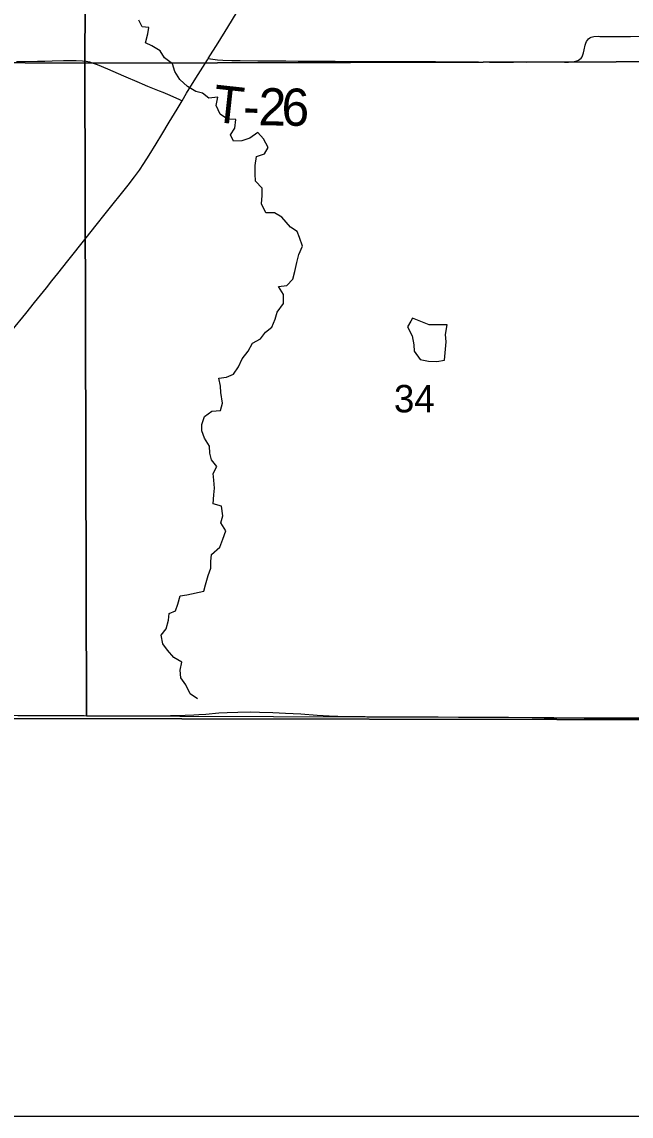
# Model space of a CAD drawing. Extents: x 0 to 34, y 0 to 22.
# Drawn here: x 3.887 to 4.352, y 14.1 to 14.935 of the extents above; entities that cross this region are included whole.
import ezdxf

# ---------------------------------------------------------------- set-up
doc = ezdxf.new("R2010")
doc.units = 0
for name, color, linetype in [('GM_X_Adjacent_County', 7, 'Continuous'), ('GM_X_County', 7, 'Continuous'), ('GM_X_County_Road', 7, 'Continuous'), ('GM_X_Minor_Lake', 7, 'Continuous'), ('GM_X_Minor_River', 7, 'Continuous'), ('GM_X_Section', 7, 'Continuous'), ('GM_X_Section_Text', 7, 'Continuous'), ('GM_X_State_Route', 7, 'Continuous'), ('GM_X_Township', 7, 'Continuous'), ('GM_X_Township_Road', 7, 'Continuous'), ('GM_X_Township_Road_Text', 7, 'Continuous'), ('SH_Data', 7, 'Continuous')]:
    doc.layers.add(name, color=color, linetype=linetype)

msp = doc.modelspace()

# ---------------------------------------------------------------- linework, layer by layer
at = {"layer": 'GM_X_Adjacent_County'}
for points in [[(2.6, 14.40919), (2.6, 14.1), (7.45277, 14.1)], [(7.45277, 14.1), (7.45284, 14.15055), (7.45459, 14.40015), (7.13726, 14.39886), (6.95145, 14.39952), (6.83768, 14.39906), (6.14063, 14.40011), (5.94628, 14.40039), (5.52367, 14.40104), (5.44111, 14.40116), (5.06657, 14.40173), (5.04041, 14.40177), (4.43815, 14.40265), (3.86539, 14.40349), (3.71208, 14.40564), (3.66948, 14.40585), (3.64498, 14.40529), (3.62218, 14.40551), (3.56097, 14.40598), (3.47236, 14.40671), (3.43312, 14.40703), (2.6, 14.40919)]]:
    msp.add_lwpolyline(points, dxfattribs=at)
at = {"layer": 'GM_X_County'}
msp.add_lwpolyline([(2.6, 14.40919), (3.43312, 14.40703), (3.47236, 14.40671), (3.56097, 14.40598), (3.62218, 14.40551), (3.64498, 14.40529), (3.66948, 14.40585), (3.71208, 14.40564), (3.86539, 14.40349), (4.43815, 14.40265)], dxfattribs=at)
at = {"layer": 'GM_X_County_Road'}
msp.add_lwpolyline([(3.88342, 14.40584), (3.8887, 14.40585), (3.8946, 14.40587), (3.89988, 14.40588), (3.90765, 14.40591), (3.91262, 14.40592), (3.91853, 14.40593), (3.92257, 14.40591), (3.92722, 14.40586), (3.93404, 14.40579), (3.93838, 14.40574), (3.94364, 14.40568), (3.95604, 14.40562), (3.9638, 14.40563), (3.97061, 14.40567), (3.97651, 14.40569), (3.98363, 14.4057), (3.98983, 14.4057), (3.99599, 14.40568), (4, 14.40578), (4.00587, 14.40599), (4.01115, 14.4062), (4.01798, 14.40638), (4.0217, 14.40657), (4.02695, 14.40699), (4.03686, 14.40787), (4.04338, 14.40826), (4.05146, 14.40852), (4.0611, 14.40861), (4.06794, 14.40852), (4.0782, 14.40822), (4.08783, 14.40778), (4.09962, 14.40703), (4.11202, 14.40612), (4.12133, 14.40556), (4.12442, 14.40539), (4.12782, 14.40526), (4.13153, 14.40514), (4.14072, 14.40508), (4.1432, 14.40503), (4.14879, 14.40499), (4.15718, 14.40497), (4.16122, 14.40496), (4.16992, 14.40493), (4.17738, 14.40492), (4.18546, 14.40488), (4.19446, 14.40483), (4.20441, 14.40475), (4.21994, 14.40461), (4.22895, 14.40464), (4.23299, 14.40465), (4.24044, 14.40467), (4.24541, 14.40464), (4.25815, 14.40453), (4.27615, 14.40432), (4.28546, 14.4042), (4.29415, 14.40412), (4.30501, 14.40407), (4.30874, 14.40401), (4.31589, 14.40389), (4.32707, 14.40383), (4.33453, 14.40377), (4.34261, 14.40368), (4.35068, 14.40363), (4.36403, 14.40365)], dxfattribs=at)
at = {"layer": 'GM_X_Minor_Lake'}
for points in [[(4.1835, 14.70693), (4.18096, 14.70257), (4.18471, 14.69571), (4.18598, 14.68887), (4.18614, 14.68394), (4.19065, 14.67765), (4.19709, 14.67646), (4.20335, 14.67622), (4.20943, 14.67731)], [(4.20943, 14.67731), (4.21048, 14.69116), (4.21014, 14.69685), (4.21133, 14.70405), (4.20469, 14.70429), (4.19767, 14.70415), (4.1848, 14.70918), (4.1835, 14.70693)]]:
    msp.add_lwpolyline(points, dxfattribs=at)
at = {"layer": 'GM_X_Minor_River'}
for points in [[(4.0385, 14.6526), (4.03834, 14.65735), (4.03706, 14.66343), (4.04276, 14.66433), (4.04827, 14.66657), (4.05211, 14.67204), (4.05481, 14.67828), (4.0594, 14.68394), (4.06267, 14.69018), (4.06877, 14.69355), (4.0726, 14.69864), (4.07756, 14.7024), (4.07988, 14.70845), (4.08144, 14.71394), (4.08623, 14.72036), (4.08647, 14.72737), (4.08253, 14.73348), (4.08879, 14.73419), (4.09357, 14.73908), (4.09494, 14.74496), (4.09651, 14.75177), (4.09807, 14.75783), (4.10096, 14.76426), (4.09855, 14.77073), (4.09668, 14.77549), (4.09158, 14.77875), (4.08519, 14.78639), (4.07952, 14.78966), (4.07288, 14.78971), (4.06951, 14.79656), (4.06994, 14.80301), (4.06998, 14.80851), (4.0649, 14.81386), (4.06475, 14.81956), (4.0646, 14.82582), (4.06579, 14.83264), (4.07188, 14.83468), (4.07457, 14.8396), (4.07101, 14.84607), (4.06668, 14.85104), (4.06058, 14.84672), (4.05449, 14.84468), (4.04823, 14.84435), (4.04599, 14.8493), (4.04906, 14.85421), (4.04987, 14.86084), (4.04361, 14.86108), (4.03795, 14.86491), (4.03496, 14.87158), (4.03614, 14.87802), (4.02931, 14.87731), (4.0244, 14.88114), (4.01929, 14.88232), (4.01305, 14.88616), (4.00721, 14.89152), (4.00346, 14.89762), (4.00161, 14.90351), (3.99557, 14.90792), (3.99219, 14.91326), (3.98577, 14.9171), (3.98085, 14.9196), (3.9828, 14.92623), (3.98359, 14.93116), (3.97829, 14.93177), (3.97586, 14.93691)], [(4.02071, 14.41861), (4.01518, 14.42253), (4.01183, 14.4292), (4.00789, 14.43474), (4.00756, 14.44043), (4.00875, 14.44669), (4.00252, 14.45015), (3.99783, 14.4557), (3.99427, 14.46066), (3.99281, 14.46713), (3.99683, 14.47203), (3.99841, 14.47866), (3.99902, 14.48378), (4.00378, 14.48583), (4.00572, 14.49094), (4.00748, 14.49719), (4.01261, 14.49791), (4.02553, 14.50084), (4.02671, 14.50577), (4.02885, 14.51277), (4.0308, 14.51826), (4.03084, 14.52358), (4.03127, 14.52889), (4.03776, 14.53434), (4.0399, 14.54059), (4.04223, 14.54683), (4.03849, 14.55294), (4.04005, 14.55824), (4.03898, 14.56565), (4.03273, 14.5676), (4.03317, 14.57443), (4.0336, 14.57955), (4.03327, 14.58563), (4.03274, 14.59076), (4.03544, 14.59605), (4.03131, 14.60102), (4.03022, 14.60616), (4.02989, 14.61147), (4.02614, 14.61758), (4.02411, 14.62329), (4.02396, 14.62804), (4.02591, 14.6341), (4.03163, 14.63823), (4.03827, 14.63874), (4.03984, 14.64423), (4.0385, 14.6526)]]:
    msp.add_lwpolyline(points, dxfattribs=at)
at = {"layer": 'GM_X_Section'}
for points in [[(3.9374, 15.40436), (3.93456, 14.90384), (3.4334, 14.90685), (3.43905, 15.40792)], [(4.4457, 15.40203), (4.44175, 14.9051), (3.93456, 14.90384), (3.9374, 15.40436)], [(3.93456, 14.90384), (3.93596, 14.4053), (3.43409, 14.40847), (3.4334, 14.90685)], [(4.44175, 14.9051), (4.43555, 14.4037), (3.93596, 14.4053), (3.93456, 14.90384)]]:
    msp.add_lwpolyline(points, close=True, dxfattribs=at)
at = {"layer": 'GM_X_State_Route'}
msp.add_lwpolyline([(3.87918, 14.69997), (3.88947, 14.71283), (3.89629, 14.7213), (3.90523, 14.73245), (3.90951, 14.73779), (3.91398, 14.74336), (3.92173, 14.75308), (3.93562, 14.77062), (3.94337, 14.78034), (3.95016, 14.78884), (3.96783, 14.81093), (3.97259, 14.81708), (3.97643, 14.82238), (3.97972, 14.8273), (3.98369, 14.83363), (3.98902, 14.84239), (3.99335, 14.84957), (3.99901, 14.85886), (4.00513, 14.86895), (4.00889, 14.87529), (4.01227, 14.88097), (4.01945, 14.89261), (4.0282, 14.90655), (4.02885, 14.90757), (4.03639, 14.91939), (4.0439, 14.93155), (4.05105, 14.9432)], dxfattribs=at)
at = {"layer": 'GM_X_Township'}
msp.add_lwpolyline([(2.6, 14.40919), (3.43312, 14.40703), (3.47236, 14.40671), (3.56097, 14.40598), (3.62218, 14.40551), (3.64498, 14.40529), (3.66948, 14.40585), (3.71208, 14.40564), (3.86539, 14.40349), (4.43815, 14.40265)], dxfattribs=at)
at = {"layer": 'GM_X_Township_Road'}
for points in [[(4.02885, 14.90757), (4.03231, 14.90708), (4.03599, 14.90656), (4.04002, 14.9063), (4.04685, 14.90611), (4.05338, 14.90596), (4.06673, 14.90572), (4.06984, 14.90569), (4.07792, 14.90563), (4.08817, 14.90571), (4.09749, 14.90547), (4.1068, 14.90537), (4.1096, 14.90536), (4.1155, 14.90539), (4.12575, 14.90547), (4.13879, 14.90531), (4.14812, 14.90516), (4.15589, 14.90515), (4.16023, 14.90514), (4.16427, 14.90514), (4.17141, 14.90516), (4.17296, 14.90517), (4.17824, 14.90521), (4.18042, 14.90522), (4.18383, 14.90516), (4.18756, 14.90518), (4.19129, 14.9051), (4.19501, 14.90515), (4.19905, 14.90517), (4.20246, 14.90511), (4.20712, 14.90507), (4.20991, 14.90507), (4.21394, 14.90502), (4.21767, 14.90503), (4.22263, 14.90498), (4.22636, 14.90497), (4.23071, 14.90489), (4.23537, 14.90488), (4.24375, 14.90482), (4.2453, 14.90483), (4.25151, 14.90478), (4.25617, 14.90484), (4.26207, 14.9048), (4.26704, 14.90486), (4.272, 14.90481), (4.27915, 14.90487), (4.28381, 14.90491), (4.28785, 14.9049), (4.29065, 14.90487), (4.29313, 14.90493), (4.2981, 14.90485), (4.3009, 14.9048), (4.30402, 14.90476), (4.30683, 14.90496), (4.30848, 14.90515), (4.31033, 14.90563), (4.31169, 14.90627), (4.31265, 14.90699), (4.3137, 14.90787), (4.31442, 14.90891), (4.31506, 14.91036), (4.31554, 14.9118), (4.3161, 14.91413), (4.31668, 14.91765), (4.31716, 14.91913), (4.31777, 14.92056), (4.31844, 14.9216), (4.31927, 14.92253), (4.32025, 14.92329), (4.32134, 14.92387), (4.32223, 14.92413), (4.32339, 14.92432), (4.32684, 14.92447), (4.32808, 14.92443), (4.33054, 14.92433), (4.33231, 14.92432), (4.33627, 14.92437), (4.34031, 14.92431), (4.34651, 14.92428), (4.35149, 14.92432), (4.36329, 14.92451)], [(3.88253, 14.90531), (3.89837, 14.90545), (3.90397, 14.90556), (3.90956, 14.90572), (3.91826, 14.90598), (3.92354, 14.90608), (3.92809, 14.906), (3.93285, 14.90574), (3.93571, 14.90544), (3.93827, 14.90496), (3.94108, 14.90408), (3.94394, 14.90292), (3.95197, 14.89957), (3.95597, 14.89785), (3.96425, 14.89429), (3.97623, 14.88911), (3.97852, 14.88815), (3.98254, 14.8865), (3.99147, 14.8829), (3.99407, 14.88187), (3.99779, 14.88029), (4.00636, 14.87643), (4.00889, 14.87529)]]:
    msp.add_lwpolyline(points, dxfattribs=at)
at = {"layer": 'SH_Data'}
msp.add_line((2.6, 14.1), (9.4, 14.1), dxfattribs=at)

# ---------------------------------------------------------------- texts
at = {"layer": 'GM_X_Section_Text'}
msp.add_text('34', height=0.020928, rotation=0.00001, dxfattribs=at).set_placement((4.1707, 14.63733))
at = {"layer": 'GM_X_Township_Road_Text'}
for s, rotation, p in [('T', 353.79303, (4.03148, 14.85935)), ('2', 359.00071, (4.06708, 14.8566)), ('6', 359.20451, (4.08469, 14.85629)), ('-', 358.66096, (4.05523, 14.85688))]:
    msp.add_text(s, height=0.02841, rotation=rotation, dxfattribs=at).set_placement(p)

doc.saveas('drawing.dxf')
